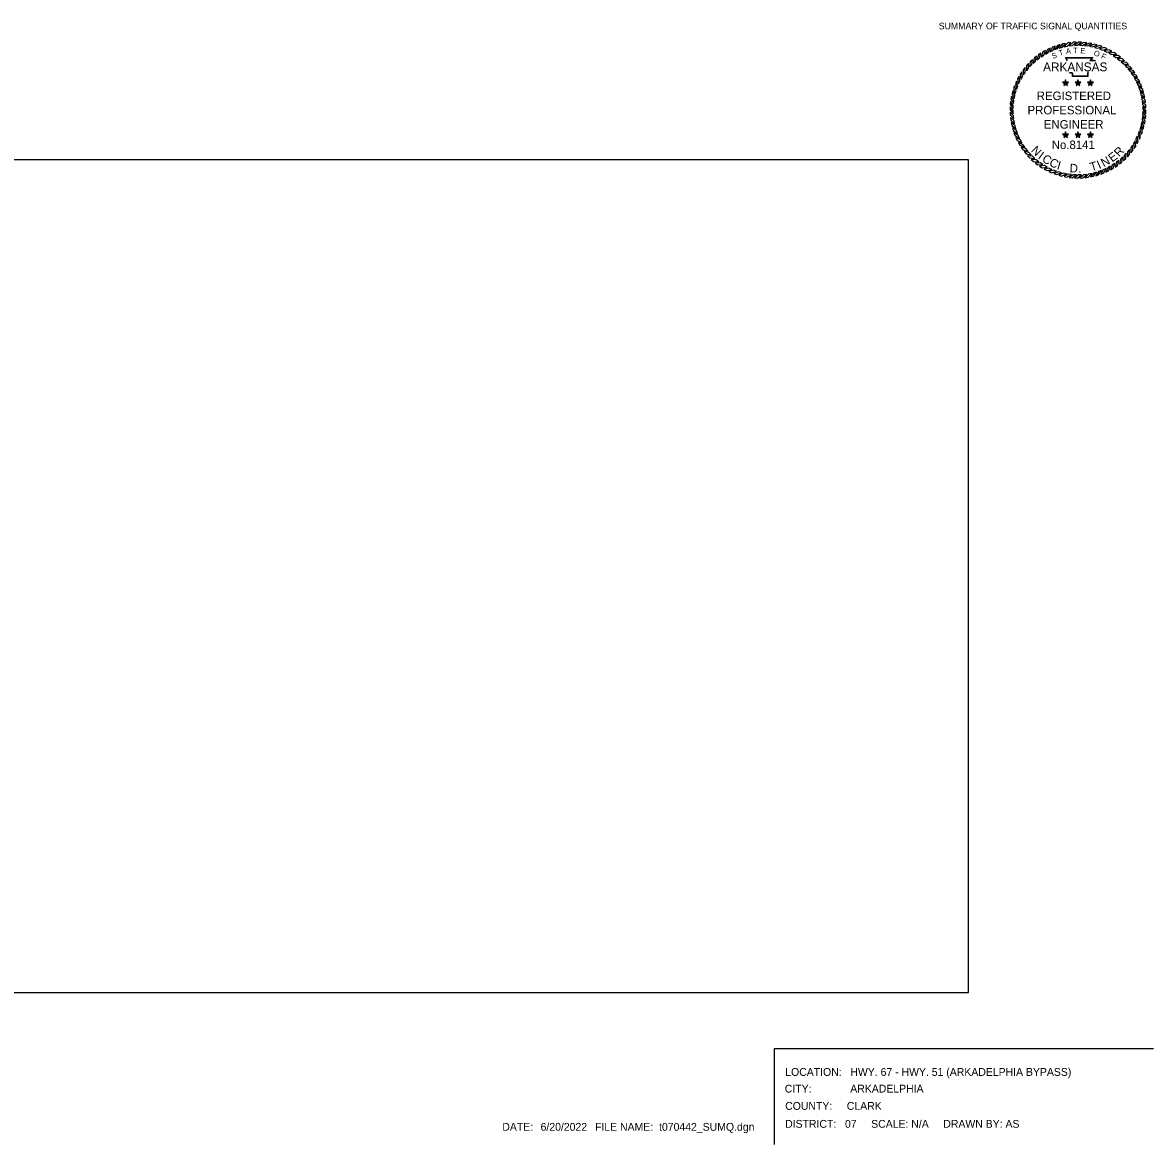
# Model space of a CAD drawing. Extents: x 418532 to 419834, y -565899 to -565297.
# Drawn here: x 419227 to 419834, y -565899 to -565297 of the extents above; entities that cross this region are included whole.
import ezdxf

# ---------------------------------------------------------------- set-up
doc = ezdxf.new("R2010")
doc.units = 0
for name, color, linetype in [('1', 7, 'Continuous'), ('G-ANNO-SYMB', 7, 'Continuous'), ('Level 10', 7, 'Continuous'), ('Level 57', 7, 'Continuous'), ('V-SIGNAL-LOOP', 7, 'Continuous')]:
    doc.layers.add(name, color=color, linetype=linetype)

msp = doc.modelspace()

# ---------------------------------------------------------------- linework, layer by layer
at = {"layer": 'G-ANNO-SYMB'}
for points in [[(419778.78, -565310.28), (419777.37, -565310.95), (419776.18, -565313.48), (419777.67, -565312.67)], [(419781.44, -565309.21), (419779.97, -565309.77), (419778.6, -565312.2), (419780.14, -565311.5)], [(419784.17, -565308.35), (419782.67, -565308.8), (419781.1, -565311.11), (419782.7, -565310.54)], [(419786.97, -565307.72), (419785.43, -565308.04), (419783.69, -565310.23), (419785.32, -565309.78)], [(419789.8, -565307.3), (419788.24, -565307.5), (419786.34, -565309.54), (419788, -565309.23)], [(419792.66, -565307.1), (419791.09, -565307.18), (419789.03, -565309.07), (419790.71, -565308.88)], [(419795.52, -565307.13), (419793.95, -565307.09), (419791.75, -565308.81), (419793.44, -565308.76)], [(419798.37, -565307.39), (419796.81, -565307.22), (419794.48, -565308.76), (419796.17, -565308.84)], [(419801.2, -565307.87), (419799.65, -565307.58), (419797.21, -565308.93), (419798.89, -565309.15)], [(419803.97, -565308.57), (419802.46, -565308.16), (419799.92, -565309.32), (419801.58, -565309.66)], [(419806.69, -565309.48), (419805.21, -565308.95), (419802.58, -565309.91), (419804.21, -565310.38)], [(419809.32, -565310.6), (419807.89, -565309.96), (419805.2, -565310.71), (419806.78, -565311.31)], [(419769.23, -565316.52), (419768.09, -565317.59), (419767.75, -565320.37), (419768.91, -565319.13)], [(419771.42, -565314.68), (419770.2, -565315.66), (419769.65, -565318.4), (419770.9, -565317.26)], [(419773.76, -565313.02), (419772.46, -565313.91), (419771.69, -565316.59), (419773.03, -565315.55)], [(419776.22, -565311.55), (419774.86, -565312.33), (419773.88, -565314.95), (419775.29, -565314.02)], [(419811.86, -565311.93), (419810.48, -565311.18), (419807.74, -565311.71), (419809.27, -565312.43)], [(419814.29, -565313.45), (419812.97, -565312.6), (419810.19, -565312.91), (419811.67, -565313.75)], [(419816.58, -565315.16), (419815.34, -565314.2), (419812.55, -565314.3), (419813.95, -565315.25)], [(419818.74, -565317.05), (419817.58, -565315.99), (419814.79, -565315.87), (419816.11, -565316.93)], [(419765.3, -565320.68), (419764.34, -565321.92), (419764.44, -565324.71), (419765.39, -565323.31)], [(419767.18, -565318.52), (419766.13, -565319.68), (419766.01, -565322.48), (419767.06, -565321.15)], [(419820.75, -565319.09), (419819.67, -565317.95), (419816.89, -565317.61), (419818.13, -565318.77)], [(419822.58, -565321.29), (419821.6, -565320.07), (419818.86, -565319.51), (419820, -565320.76)], [(419824.24, -565323.62), (419823.36, -565322.33), (419820.67, -565321.56), (419821.71, -565322.9)], [(419760.74, -565327.94), (419760.1, -565329.37), (419760.84, -565332.07), (419761.44, -565330.48)], [(419762.07, -565325.4), (419761.31, -565326.78), (419761.85, -565329.52), (419762.57, -565327.99)], [(419763.59, -565322.98), (419762.73, -565324.29), (419763.05, -565327.07), (419763.89, -565325.6)], [(419787.03, -565329.04), (419786.65, -565328.52), (419785.44, -565328.52), (419786.42, -565329.24)], [(419787.03, -565329.04), (419787.4, -565328.52), (419787.03, -565327.37), (419786.65, -565328.52)], [(419787.03, -565329.04), (419787.63, -565329.24), (419788.61, -565328.52), (419787.4, -565328.52)], [(419793.7, -565329.04), (419793.32, -565328.52), (419792.11, -565328.52), (419793.09, -565329.24)], [(419793.7, -565329.04), (419794.07, -565328.52), (419793.7, -565327.37), (419793.32, -565328.52)], [(419793.7, -565329.04), (419794.3, -565329.24), (419795.28, -565328.52), (419794.07, -565328.52)], [(419800.37, -565329.04), (419799.99, -565328.52), (419798.78, -565328.52), (419799.76, -565329.24)], [(419800.37, -565329.04), (419800.74, -565328.52), (419800.37, -565327.37), (419799.99, -565328.52)], [(419800.37, -565329.04), (419800.97, -565329.24), (419801.95, -565328.52), (419800.74, -565328.52)], [(419825.71, -565326.08), (419824.93, -565324.72), (419822.31, -565323.74), (419823.24, -565325.16)], [(419826.98, -565328.65), (419826.31, -565327.23), (419823.78, -565326.05), (419824.6, -565327.53)], [(419828.05, -565331.31), (419827.49, -565329.84), (419825.06, -565328.46), (419825.76, -565330.01)], [(419758.7, -565333.29), (419758.29, -565334.8), (419759.45, -565337.35), (419759.79, -565335.69)], [(419759.61, -565330.57), (419759.09, -565332.05), (419760.04, -565334.68), (419760.52, -565333.05)], [(419787.03, -565329.04), (419786.42, -565329.24), (419786.05, -565330.39), (419787.03, -565329.68)], [(419787.03, -565329.04), (419787.03, -565329.68), (419788.01, -565330.39), (419787.63, -565329.24)], [(419793.7, -565329.04), (419793.09, -565329.24), (419792.72, -565330.39), (419793.7, -565329.68)], [(419793.7, -565329.04), (419793.7, -565329.68), (419794.68, -565330.39), (419794.3, -565329.24)], [(419800.37, -565329.04), (419799.76, -565329.24), (419799.39, -565330.39), (419800.37, -565329.68)], [(419800.37, -565329.04), (419800.37, -565329.68), (419801.35, -565330.39), (419800.97, -565329.24)], [(419828.91, -565334.04), (419828.47, -565332.53), (419826.15, -565330.97), (419826.72, -565332.56)], [(419829.55, -565336.83), (419829.22, -565335.3), (419827.04, -565333.55), (419827.48, -565335.19)], [(419757.52, -565338.89), (419757.36, -565340.45), (419758.9, -565342.78), (419758.98, -565341.09)], [(419758, -565336.07), (419757.71, -565337.61), (419759.07, -565340.05), (419759.28, -565338.37)], [(419829.96, -565339.66), (419829.76, -565338.11), (419827.72, -565336.2), (419828.04, -565337.87)], [(419830.16, -565342.52), (419830.08, -565340.95), (419828.19, -565338.89), (419828.38, -565340.58)], [(419757.27, -565341.74), (419757.22, -565343.31), (419758.95, -565345.51), (419758.89, -565343.82)], [(419757.24, -565344.61), (419757.32, -565346.17), (419759.21, -565348.23), (419759.02, -565346.55)], [(419829.87, -565348.24), (419830.04, -565346.68), (419828.5, -565344.35), (419828.42, -565346.04)], [(419830.13, -565345.38), (419830.17, -565343.82), (419828.45, -565341.61), (419828.51, -565343.31)], [(419757.43, -565347.46), (419757.63, -565349.02), (419759.68, -565350.93), (419759.36, -565349.26)], [(419757.85, -565350.3), (419758.17, -565351.83), (419760.36, -565353.57), (419759.91, -565351.94)], [(419758.49, -565353.09), (419758.93, -565354.59), (419761.25, -565356.16), (419760.67, -565354.56)], [(419827.78, -565356.55), (419828.31, -565355.08), (419827.35, -565352.45), (419826.88, -565354.08)], [(419828.7, -565353.84), (419829.11, -565352.32), (419827.95, -565349.78), (419827.6, -565351.44)], [(419829.39, -565351.06), (419829.68, -565349.52), (419828.33, -565347.07), (419828.12, -565348.76)], [(419759.34, -565355.82), (419759.9, -565357.29), (419762.34, -565358.66), (419761.64, -565357.12)], [(419760.41, -565358.48), (419761.08, -565359.9), (419763.62, -565361.08), (419762.8, -565359.59)], [(419787.03, -565356.97), (419786.65, -565356.45), (419785.44, -565356.45), (419786.42, -565357.17)], [(419787.03, -565356.97), (419786.42, -565357.17), (419786.05, -565358.32), (419787.03, -565357.61)], [(419787.03, -565356.97), (419787.4, -565356.45), (419787.03, -565355.3), (419786.65, -565356.45)], [(419787.03, -565356.97), (419787.63, -565357.17), (419788.61, -565356.45), (419787.4, -565356.45)], [(419787.03, -565356.97), (419787.03, -565357.61), (419788.01, -565358.32), (419787.63, -565357.17)], [(419793.7, -565356.97), (419793.32, -565356.45), (419792.11, -565356.45), (419793.09, -565357.17)], [(419793.7, -565356.97), (419793.09, -565357.17), (419792.72, -565358.32), (419793.7, -565357.61)], [(419793.7, -565356.97), (419794.07, -565356.45), (419793.7, -565355.3), (419793.32, -565356.45)], [(419793.7, -565356.97), (419794.3, -565357.17), (419795.28, -565356.45), (419794.07, -565356.45)], [(419793.7, -565356.97), (419793.7, -565357.61), (419794.68, -565358.32), (419794.3, -565357.17)], [(419800.37, -565356.97), (419799.99, -565356.45), (419798.78, -565356.45), (419799.76, -565357.17)], [(419800.37, -565356.97), (419799.76, -565357.17), (419799.39, -565358.32), (419800.37, -565357.61)], [(419800.37, -565356.97), (419800.74, -565356.45), (419800.37, -565355.3), (419799.99, -565356.45)], [(419800.37, -565356.97), (419800.97, -565357.17), (419801.95, -565356.45), (419800.74, -565356.45)], [(419800.37, -565356.97), (419800.37, -565357.61), (419801.35, -565358.32), (419800.97, -565357.17)], [(419825.33, -565361.73), (419826.08, -565360.35), (419825.55, -565357.6), (419824.83, -565359.14)], [(419826.66, -565359.19), (419827.3, -565357.76), (419826.55, -565355.06), (419825.95, -565356.65)], [(419761.69, -565361.05), (419762.47, -565362.41), (419765.09, -565363.38), (419764.15, -565361.97)], [(419763.16, -565363.5), (419764.04, -565364.8), (419766.73, -565365.57), (419765.69, -565364.23)], [(419820.22, -565368.61), (419821.27, -565367.44), (419821.39, -565364.65), (419820.33, -565365.97)], [(419822.1, -565366.45), (419823.06, -565365.21), (419822.96, -565362.41), (419822.01, -565363.82)], [(419823.81, -565364.15), (419824.67, -565362.84), (419824.35, -565360.06), (419823.51, -565361.53)], [(419764.81, -565365.84), (419765.8, -565367.06), (419768.54, -565367.62), (419767.4, -565366.36)], [(419766.65, -565368.04), (419767.73, -565369.18), (419770.5, -565369.52), (419769.27, -565368.36)], [(419768.65, -565370.08), (419769.82, -565371.13), (419772.61, -565371.26), (419771.29, -565370.2)], [(419813.64, -565374.11), (419814.93, -565373.22), (419815.7, -565370.53), (419814.36, -565371.57)], [(419815.97, -565372.45), (419817.19, -565371.46), (419817.75, -565368.72), (419816.5, -565369.86)], [(419818.17, -565370.61), (419819.31, -565369.53), (419819.65, -565366.76), (419818.49, -565367.99)], [(419770.81, -565371.97), (419772.05, -565372.92), (419774.85, -565372.83), (419773.45, -565371.87)], [(419773.11, -565373.67), (419774.42, -565374.53), (419777.2, -565374.21), (419775.73, -565373.37)], [(419775.54, -565375.2), (419776.91, -565375.95), (419779.66, -565375.41), (419778.12, -565374.69)], [(419778.07, -565376.52), (419779.51, -565377.16), (419782.2, -565376.42), (419780.61, -565375.82)], [(419780.71, -565377.65), (419782.19, -565378.17), (419784.81, -565377.22), (419783.19, -565376.75)], [(419800.43, -565379.41), (419801.97, -565379.09), (419803.71, -565376.9), (419802.07, -565377.35)], [(419803.22, -565378.77), (419804.73, -565378.33), (419806.29, -565376.01), (419804.7, -565376.59)], [(419805.96, -565377.92), (419807.42, -565377.36), (419808.8, -565374.93), (419807.25, -565375.62)], [(419808.61, -565376.85), (419810.03, -565376.18), (419811.21, -565373.64), (419809.73, -565374.46)], [(419811.18, -565375.58), (419812.54, -565374.8), (419813.52, -565372.18), (419812.1, -565373.11)], [(419783.42, -565378.56), (419784.94, -565378.97), (419787.48, -565377.81), (419785.82, -565377.47)], [(419786.2, -565379.26), (419787.74, -565379.55), (419790.19, -565378.19), (419788.51, -565377.98)], [(419789.02, -565379.74), (419790.58, -565379.91), (419792.92, -565378.36), (419791.22, -565378.28)], [(419791.88, -565379.99), (419793.44, -565380.04), (419795.65, -565378.32), (419793.95, -565378.37)], [(419794.74, -565380.02), (419796.31, -565379.95), (419798.37, -565378.06), (419796.68, -565378.24)], [(419797.6, -565379.83), (419799.15, -565379.63), (419801.06, -565377.58), (419799.4, -565377.9)]]:
    msp.add_lwpolyline(points, close=True, dxfattribs=at)
for points in [[(419787.85, -565317.09), (419787, -565315.25), (419801.72, -565315.24), (419800.49, -565316.78), (419801.49, -565316.77), (419802.32, -565316.76), (419803.16, -565316.85)], [(419788.07, -565316.99), (419787.37, -565315.48), (419801.23, -565315.47), (419800, -565317.02), (419801.49, -565317), (419802.31, -565316.99), (419803.13, -565317.08)], [(419799.4, -565323.26), (419799.15, -565323.46), (419799.06, -565323.77), (419798.98, -565324.53), (419798.98, -565325.54), (419790.77, -565325.54), (419790.77, -565324.17), (419790.77, -565323.87), (419790.44, -565323.77), (419789.27, -565323.77), (419789.06, -565323.45)], [(419799.25, -565323.08), (419798.94, -565323.33), (419798.83, -565323.72), (419798.75, -565324.52), (419798.75, -565325.31), (419791, -565325.31), (419791, -565324.17), (419791, -565323.69), (419790.47, -565323.53), (419789.39, -565323.53), (419789.25, -565323.32)]]:
    msp.add_lwpolyline(points, dxfattribs=at)
at = {"layer": 'Level 57'}
for points in [[(419630.59, -565847.55), (419630.59, -565898.75)], [(419834.17, -565847.55), (419630.59, -565847.55)]]:
    msp.add_lwpolyline(points, dxfattribs=at)
at = {"layer": 'V-SIGNAL-LOOP'}
msp.add_lwpolyline([(418969.24, -565817.28), (419734.87, -565817.28), (419734.87, -565370.24), (418969.24, -565370.24)], close=True, dxfattribs=at)

# ---------------------------------------------------------------- texts
at = {"layer": '1'}
msp.add_text('SUMMARY OF TRAFFIC SIGNAL QUANTITIES', height=3.5172, rotation=360, dxfattribs=at).set_placement((419718.96, -565300.17))
at = {"layer": 'G-ANNO-SYMB'}
for s, height, rotation, p in [('A', 2.9, 8.67877, (419787.41, -565313.55)), ('T', 2.9, 1.47887, (419791.15, -565312.97)), ('E', 2.9, 356.67203, (419794.87, -565313.06)), ('S', 2.9, 19.77256, (419780.19, -565316.13)), ('T', 2.9, 16.90148, (419783.88, -565314.47)), ('O', 2.9, 341.2218, (419801.91, -565314.05)), ('F', 2.9, 335.36282, (419805.83, -565315.58)), ('N', 4.59, 315.26758, (419768.22, -565365.56)), ('R', 4.59, 45.47796, (419815.79, -565368.96)), ('I', 4.59, 324.21406, (419771.95, -565369.26)), ('C', 4.59, 328.68731, (419774.02, -565370.88)), ('C', 4.59, 336.51548, (419777.92, -565373.3)), ('I', 4.59, 344.34365, (419782.12, -565375.17)), ('T', 4.59, 16.77466, (419800.88, -565376.45)), ('I', 4.59, 24.23006, (419805.08, -565375.24)), ('N', 4.59, 28.7033, (419807.52, -565374.26)), ('E', 4.59, 37.64979, (419812.12, -565371.74)), ('D', 4.59, 356.64507, (419789.12, -565376.91)), ('.', 4.59, 4.84601, (419793.92, -565377.23))]:
    msp.add_text(s, height=height, rotation=rotation, dxfattribs=at).set_placement(p)
for s, height, p in [('ARKANSAS', 4.737, (419774.98, -565322.73)), ('REGISTERED', 4.585, (419771.54, -565338.19)), ('PROFESSIONAL', 4.5855, (419766.62, -565345.86)), ('ENGINEER', 4.585, (419775.36, -565353.52)), ('No.8141', 4.567, (419779.63, -565364.46))]:
    msp.add_text(s, height=height, dxfattribs=at).set_placement(p)
at = {"layer": 'Level 10'}
for s, p in [('LOCATION:   HWY. 67 - HWY. 51 (ARKADELPHIA BYPASS)', (419636.58, -565861.97)), ('CITY:', (419636.32, -565870.93)), (' ARKADELPHIA', (419669.92, -565870.93)), ('COUNTY:     CLARK', (419636.53, -565880.2)), ('DATE:  ', (419484.7, -565891.43)), ('6/20/2022', (419505.24, -565891.43)), ('  FILE NAME: ', (419531.34, -565891.43)), ('t070442_SUMQ.dgn', (419568.83, -565891.43)), ('DISTRICT:   07     SCALE: N/A     DRAWN BY: AS', (419636.51, -565889.83))]:
    msp.add_text(s, height=4.2, rotation=360, dxfattribs=at).set_placement(p)

doc.saveas('drawing.dxf')
